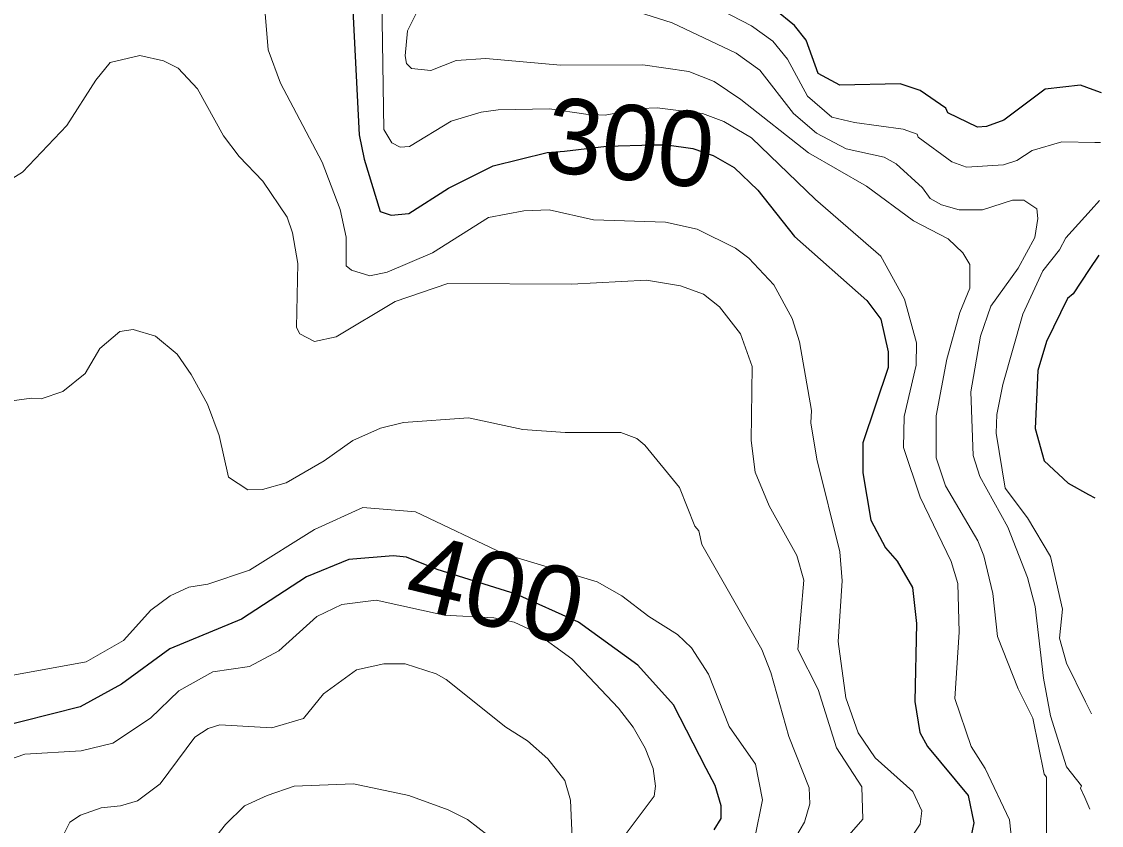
# Model space of a CAD drawing. Extents: x 673.3 to 698.5, y 6984.3 to 7012.3.
# Drawn here: x 696.93 to 698.08, y 6987.096 to 6987.951 of the extents above; entities that cross this region are included whole.
import ezdxf
from ezdxf.enums import TextEntityAlignment as Align

# ---------------------------------------------------------------- set-up
doc = ezdxf.new("R2010")
doc.units = 0
doc.header["$LTSCALE"] = 0.032
doc.layers.add('1', color=7, linetype='Continuous', lineweight=25)
doc.layers.add('2', color=7, linetype='Continuous', lineweight=13)
doc.layers.add('61', color=7, linetype='Continuous')

msp = doc.modelspace()

# ---------------------------------------------------------------- linework, layer by layer
at = {"layer": '1'}
for points in [[(697.2824, 6987.9775), (697.2897, 6987.8309), (697.2951, 6987.8049), (697.3121, 6987.7491), (697.3239, 6987.7452), (697.3427, 6987.747), (697.3848, 6987.774), (697.4324, 6987.7977), (697.4898, 6987.8119), (697.5083, 6987.8134), (697.553, 6987.8187), (697.6028, 6987.82), (697.617, 6987.8202), (697.6448, 6987.8162), (697.6665, 6987.8087), (697.6888, 6987.796), (697.714, 6987.7719), (697.7529, 6987.7225), (697.83, 6987.6544), (697.8449, 6987.6344), (697.8525, 6987.5996), (697.8525, 6987.583), (697.8256, 6987.5029), (697.8256, 6987.4709), (697.8343, 6987.4206), (697.8496, 6987.3913), (697.8622, 6987.377), (697.8785, 6987.349), (697.8826, 6987.3107), (697.8811, 6987.2277), (697.8862, 6987.1946), (697.8945, 6987.1796), (697.9379, 6987.1277), (697.9436, 6987.0984), (697.9403, 6987.0814)], [(698.0795, 6987.8753), (698.0708, 6987.8786), (698.0574, 6987.8837), (698.0198, 6987.8795), (697.9757, 6987.8463), (697.9573, 6987.8396), (697.9475, 6987.8388), (697.9162, 6987.8541), (697.914, 6987.8593), (697.8867, 6987.8778), (697.8655, 6987.885), (697.8012, 6987.8836), (697.7782, 6987.8961), (697.7653, 6987.9316), (697.7531, 6987.947), (697.7319, 6987.9641)], [(698.0767, 6987.7026), (698.0665, 6987.6873), (698.0493, 6987.6615), (698.0435, 6987.6565), (698.021, 6987.6107), (698.0118, 6987.58), (698.009, 6987.5183), (698.0187, 6987.4837), (698.0441, 6987.4599), (698.0659, 6987.4479), (698.0726, 6987.4442)], [(697.6673, 6987.091), (697.6749, 6987.1029), (697.6749, 6987.1164), (697.6684, 6987.1381), (697.6591, 6987.1561), (697.624, 6987.2241), (697.5861, 6987.2662), (697.5231, 6987.312), (697.4567, 6987.3419), (697.3728, 6987.3682), (697.3402, 6987.3811), (697.3259, 6987.3827), (697.2786, 6987.3787), (697.2338, 6987.3603), (697.1646, 6987.3153), (697.0881, 6987.2835), (697.0367, 6987.2461), (696.9929, 6987.222), (696.8999, 6987.1984)]]:
    msp.add_lwpolyline(points, dxfattribs=at)
at = {"layer": '2'}
for points in [[(697.3133, 6987.999), (697.3158, 6987.8366), (697.3246, 6987.8221), (697.3335, 6987.8177), (697.3432, 6987.8183), (697.3875, 6987.8452), (697.4195, 6987.8549), (697.4377, 6987.8574), (697.4923, 6987.8583), (697.531, 6987.8527), (697.5516, 6987.8516), (697.5895, 6987.8589), (697.6067, 6987.8595), (697.6549, 6987.8534), (697.6777, 6987.8451), (697.7073, 6987.8275), (697.7754, 6987.762), (697.8449, 6987.7015), (697.8699, 6987.6558), (697.8826, 6987.6094), (697.8825, 6987.5857), (697.8696, 6987.5309), (697.8688, 6987.4981), (697.8867, 6987.445), (697.9198, 6987.3767), (697.9266, 6987.3532), (697.9283, 6987.3013), (697.9234, 6987.2307), (697.941, 6987.1797), (697.9558, 6987.1563), (697.9816, 6987.1015), (697.9868, 6987.0557)], [(697.6318, 6987.9863), (697.707, 6987.9469), (697.7299, 6987.9303), (697.7455, 6987.9112), (697.7666, 6987.8718), (697.7925, 6987.8496), (697.8168, 6987.8437), (697.8685, 6987.8369), (697.8833, 6987.8313), (697.8845, 6987.8281), (697.9204, 6987.802), (697.9361, 6987.7965), (697.9752, 6987.7988), (697.9896, 6987.8036), (698.0058, 6987.8139), (698.0373, 6987.8232), (698.0724, 6987.8226), (698.0786, 6987.8225)], [(698.021, 6987.0759), (698.0211, 6987.1471), (698.0187, 6987.1501), (698.0064, 6987.2098), (697.9911, 6987.2409), (697.969, 6987.2967), (697.9639, 6987.3426), (697.9543, 6987.3825), (697.948, 6987.3985), (697.9137, 6987.4571), (697.9038, 6987.487), (697.9038, 6987.5315), (697.9149, 6987.5918), (697.929, 6987.6417), (697.9396, 6987.6675), (697.9396, 6987.6927), (697.9322, 6987.7052), (697.9166, 6987.72), (697.8796, 6987.7393), (697.8296, 6987.776), (697.7678, 6987.8116), (697.6959, 6987.8682), (697.6676, 6987.8876), (697.6405, 6987.898), (697.5917, 6987.9054), (697.5038, 6987.9048), (697.4245, 6987.9121), (697.3929, 6987.9097), (697.3661, 6987.8994), (697.3454, 6987.9014), (697.3402, 6987.9068), (697.3387, 6987.9149), (697.3411, 6987.9416), (697.3588, 6987.9773)], [(698.0673, 6987.113), (698.0617, 6987.1253), (698.0571, 6987.1354), (698.0582, 6987.1379), (698.0423, 6987.1581), (698.0254, 6987.2122), (698.0178, 6987.2524), (698.0089, 6987.3287), (698.0007, 6987.3597), (697.9798, 6987.4131), (697.9503, 6987.4672), (697.943, 6987.4896), (697.9407, 6987.5571), (697.9508, 6987.6166), (697.9617, 6987.6485), (697.9908, 6987.6887), (698.0087, 6987.7213), (698.0119, 6987.7417), (698.0108, 6987.7521), (697.9971, 6987.7613), (697.9848, 6987.7612), (697.9529, 6987.7509), (697.9281, 6987.751), (697.9092, 6987.7563), (697.8973, 6987.763), (697.8893, 6987.7742), (697.8612, 6987.7998), (697.8483, 6987.8069), (697.8079, 6987.816), (697.7765, 6987.8324), (697.7517, 6987.8534), (697.7159, 6987.8995), (697.6907, 6987.9176), (697.6226, 6987.9501), (697.5445, 6987.9752)], [(697.8744, 6987.0782), (697.8865, 6987.0969), (697.8883, 6987.1112), (697.8787, 6987.1317), (697.8389, 6987.1675), (697.8205, 6987.1944), (697.8076, 6987.2315), (697.7995, 6987.2915), (697.8037, 6987.3559), (697.8012, 6987.387), (697.7767, 6987.4856), (697.7703, 6987.5242), (697.771, 6987.5374), (697.7581, 6987.6104), (697.7506, 6987.6352), (697.731, 6987.6712), (697.7045, 6987.6993), (697.6902, 6987.7102), (697.6495, 6987.7305), (697.6158, 6987.7377), (697.5389, 6987.7404), (697.492, 6987.7508), (697.465, 6987.7499), (697.4273, 6987.7426), (697.3677, 6987.705), (697.3196, 6987.6845), (697.3009, 6987.6808), (697.2814, 6987.6866), (697.2757, 6987.6914), (697.2758, 6987.7218), (697.2695, 6987.7511), (697.2505, 6987.8016), (697.2059, 6987.8857), (697.193, 6987.9212), (697.1896, 6987.96)], [(696.9051, 6987.7751), (696.9316, 6987.7909), (696.9788, 6987.8406), (697.0094, 6987.889), (697.0248, 6987.9076), (697.0562, 6987.9153)], [(697.0562, 6987.9153), (697.0815, 6987.9096), (697.097, 6987.9018), (697.1177, 6987.8797), (697.1453, 6987.8298), (697.1621, 6987.8077), (697.1873, 6987.7815), (697.213, 6987.743), (697.2188, 6987.7264), (697.2245, 6987.6938), (697.223, 6987.6255), (697.2264, 6987.6189), (697.2421, 6987.6108), (697.2651, 6987.6157), (697.3279, 6987.6534), (697.3842, 6987.6726), (697.5158, 6987.6718), (697.5956, 6987.6759), (697.6315, 6987.6702), (697.6562, 6987.6612), (697.6733, 6987.6475), (697.6955, 6987.6191), (697.708, 6987.584), (697.7067, 6987.5055), (697.7112, 6987.4717), (697.7258, 6987.4357), (697.7554, 6987.383), (697.7628, 6987.3566), (697.7564, 6987.2829), (697.778, 6987.2403), (697.7975, 6987.1784), (697.8247, 6987.1367), (697.8255, 6987.1022), (697.811, 6987.0856)], [(698.0776, 6987.7609), (698.0687, 6987.751), (698.0418, 6987.7212), (698.0348, 6987.7084), (698.0171, 6987.6859), (697.9958, 6987.6398), (697.9746, 6987.5651), (697.9682, 6987.5331), (697.9674, 6987.5132), (697.977, 6987.4546), (698.0008, 6987.4232), (698.0253, 6987.3821), (698.0381, 6987.326), (698.035, 6987.2951), (698.0424, 6987.2685), (698.0627, 6987.2272), (698.0689, 6987.2146)], [(697.7543, 6987.0834), (697.7637, 6987.0993), (697.7694, 6987.1188), (697.7685, 6987.1356), (697.747, 6987.1903), (697.7279, 6987.2586), (697.7182, 6987.2831), (697.6542, 6987.3948), (697.6513, 6987.4093), (697.647, 6987.4142), (697.6304, 6987.4555), (697.5937, 6987.5006), (697.5851, 6987.5074), (697.5683, 6987.514), (697.509, 6987.5139), (697.464, 6987.517), (697.4062, 6987.5294), (697.3368, 6987.5244), (697.3125, 6987.5187), (697.283, 6987.5055), (697.2525, 6987.4838), (697.2121, 6987.4603), (697.1867, 6987.4532), (697.1714, 6987.4529), (697.1506, 6987.4665), (697.1409, 6987.5108), (697.1283, 6987.5442), (697.1111, 6987.5757), (697.0959, 6987.5974), (697.0729, 6987.6166), (697.0493, 6987.6237), (697.0351, 6987.6214), (697.0138, 6987.6033), (696.9983, 6987.5768), (696.9743, 6987.5576), (696.9512, 6987.5497), (696.9412, 6987.5504), (696.8804, 6987.5422)], [(696.8449, 6987.2418), (696.9992, 6987.2699), (697.0391, 6987.2925), (697.068, 6987.3247), (697.0887, 6987.3402), (697.1086, 6987.3492), (697.1288, 6987.3526), (697.1731, 6987.3675), (697.2421, 6987.4107), (697.2936, 6987.4341), (697.3495, 6987.4293), (697.4437, 6987.3847), (697.5429, 6987.3548), (697.5691, 6987.3401), (697.5978, 6987.3182), (697.6283, 6987.299), (697.6433, 6987.2848)], [(697.5674, 6987.0785), (697.6037, 6987.1267), (697.6049, 6987.1374), (697.6025, 6987.1561), (697.5942, 6987.1778), (697.5814, 6987.2001), (697.5657, 6987.2206), (697.5159, 6987.2729), (697.4758, 6987.302), (697.4546, 6987.3121), (697.433, 6987.3168), (697.3801, 6987.3194), (697.3079, 6987.3354), (697.2711, 6987.3308), (697.2447, 6987.3182), (697.2042, 6987.2815), (697.1731, 6987.2649), (697.1339, 6987.259), (697.0979, 6987.239), (697.0678, 6987.2097), (697.0275, 6987.1832), (696.9939, 6987.1751), (696.9341, 6987.1716), (696.8989, 6987.1595)], [(697.6433, 6987.2848), (697.6613, 6987.2568), (697.6835, 6987.2009), (697.7116, 6987.161), (697.7189, 6987.1231), (697.7108, 6987.0826)], [(696.9752, 6987.0857), (696.982, 6987.0993), (696.9933, 6987.1066), (697.015, 6987.1144), (697.0359, 6987.1165), (697.0539, 6987.1217), (697.0778, 6987.1398), (697.115, 6987.1896), (697.1291, 6987.1989), (697.1415, 6987.2027), (697.1966, 6987.1994), (697.2303, 6987.2095), (697.2519, 6987.2358), (697.2867, 6987.2613), (697.3158, 6987.2678), (697.3386, 6987.2678), (697.3715, 6987.2571), (697.3824, 6987.2509), (697.4459, 6987.2004), (697.4687, 6987.1858), (697.4905, 6987.1664), (697.5086, 6987.1436), (697.5144, 6987.1227), (697.5186, 6987.0335)], [(697.4381, 6987.0763), (697.4051, 6987.1019), (697.3845, 6987.1122), (697.3424, 6987.1276), (697.2838, 6987.14), (697.2207, 6987.1374), (697.1918, 6987.1277), (697.1677, 6987.1164), (697.1473, 6987.0968), (697.1343, 6987.08)]]:
    msp.add_lwpolyline(points, dxfattribs=at)

# ---------------------------------------------------------------- texts
at = {"layer": '61'}
msp.add_text('300', height=0.08, rotation=353.938, dxfattribs=at).set_placement((697.5739, 6987.7828), align=Align.CENTER)
at = {"layer": '61', "width": 1.05}
msp.add_text('400', height=0.08, rotation=346.475, dxfattribs=at).set_placement((697.4259, 6987.3081), align=Align.CENTER)

doc.saveas('drawing.dxf')
